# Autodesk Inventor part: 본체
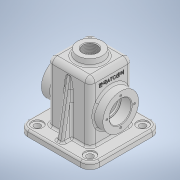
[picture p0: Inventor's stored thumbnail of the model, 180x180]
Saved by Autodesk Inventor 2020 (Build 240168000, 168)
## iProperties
Created: 2021-07
Part Number: 본체
Material: 일반
Document SubType Name: Modeling
Designer: Owner
Density: 1 g/cm^3
Appearance: 기본값
Author: Owner
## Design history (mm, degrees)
sketch "스케치1"
  geometry: L1 (34, 34)-(-34, 34); L2 (-34, 34)-(-34, -34); L3 (-34, -34)-(34, -34); L4 (34, -34)-(34, 34); L5 (34, 34)-(-34, -34); L6 (-34, 34)-(34, -34); 1 further point
  constraints: 12 end point, 2 midpoint, 2 parallel, 1 horizontal, 1 perpendicular
  dimensions: "d0" = 68 distance of L3.end L2.end; "d1" = 68 distance of L2.end L1.end
extrude "돌출1" new body sketch "스케치1" distance "d2" = 95; taper "d3" = 0 deg
fillet "모깎기1" dims "d4" = 8
feature "쉘1" dims "d5" = 5
node "작업 평면1"
sketch "스케치2"
  geometry: C1 r 20 at (0, 0); 1 further point
  constraints: 1 centre point, 1 coincident
  dimensions: "d7" = 40 diameter of C1
extrude "돌출2" join sketch "스케치2" stored distance "d8" = 95; taper "d9" = 8 deg
sketch "스케치3"
  geometry: L1 (57, -57)-(-57, -57); L2 (-57, -57)-(-57, 57); L3 (-57, 57)-(57, 57); L4 (57, 57)-(57, -57); L5 (57, -57)-(-57, 57); L6 (-57, -57)-(57, 57); L7 (-29, -26)-(-29, 26) reference; L8 (26, -29)-(-26, -29) reference; L9 (29, 26)-(29, -26) reference; L10 (-26, 29)-(26, 29) reference; A1 r 3 centre (-26, -26) between (-29, -26) and (-26, -29) reference; A2 r 3 centre (26, -26) between (26, -29) and (29, -26) reference; A3 r 3 centre (-26, 26) between (-26, 29) and (-29, 26) reference; A4 r 3 centre (26, 26) between (29, 26) and (26, 29) reference; 1 further point
  constraints: 12 end point, 2 midpoint, 2 parallel, 1 horizontal, 1 perpendicular
  dimensions: "d10" = 114 distance of L2.end L3.end; "d11" = 114 distance of L1.end L2.end
extrude "돌출3" join sketch "스케치3" distance "d12" = 10; taper "d13" = 0 deg
fillet "모깎기2" dims "d14" = 15
sketch "스케치4"
  geometry: A1 r 15 centre (42, -42) between (42, -57) and (57, -42) reference; A2 r 15 centre (-42, -42) between (-57, -42) and (-42, -57) reference; A3 r 15 centre (42, 42) between (57, 42) and (42, 57) reference; A4 r 15 centre (-42, 42) between (-42, 57) and (-57, 42) reference; 5 further points
  constraints: 4 coincident
hole "구멍1" sketch "스케치4" at (42, -42), (-42, -42), (42, 42), (-42, 42) diameter "d15" = 10; stored, may be unused: countersink angle "d19" = 90 deg, drill point angle "d21" = 0 deg; dims "d16" = 8, "d17" = 18, "d18" = 2, "d20" = 10
sketch "스케치5"
  geometry: C1 r 20 at (0, 0) reference; 2 further points
  constraints: 1 coincident
hole "구멍2" sketch "스케치5" at (0, 0) diameter "d22" = 22.83494; stored, may be unused: countersink angle "d26" = 90 deg, drill point angle "d28" = 0 deg; dims "d23" = 20, "d24" = 18, "d25" = 2, "d27" = 20
node "작업 평면2"
sketch "스케치6"
  geometry: C1 r 28.5 at (42, 0); 1 further point
  constraints: 1 centre point, 1 horizontal alignment
  dimensions: "d30" = 57 diameter of C1; "d31" = 42 distance of point (0, 0) C1.centre
extrude "돌출4" join sketch "스케치6" stored distance "d32" = 10; taper "d33" = 0 deg
sketch "스케치7"
  geometry: C1 r 28.5 at (0, 0) reference; C2 r 17.5 at (0, 0); 1 further point
  constraints: 1 centre point, 1 coincident
  dimensions: "d34" = 35 diameter of C2
extrude "돌출5" cut sketch "스케치7" distance "d35" = 17; taper "d36" = 0 deg
sketch "스케치8"
  geometry: C1 r 17.5 at (0, 0) reference; C2 r 15 at (0, 0); 1 further point
  constraints: 1 centre point, 1 coincident
  dimensions: "d37" = 30 diameter of C2
extrude "돌출6" cut sketch "스케치8" stored distance "d38" = 17; taper "d39" = 0 deg
sketch "스케치9"
  geometry: L1 (6, 18)-(46, 18) reference; L2 (-8, 0)-(-8, -87) reference; 2 further points
  constraints: 1 other
  dimensions: "d40" = 25 distance from line of L1 point (26, -7); "d41" = 34 distance from line of L2 point (26, -7)
feature "엠보싱1" sketch "스케치9" dims "d0" = 68, "d1" = 68, "d42" = 0.5, "d43" = 0
sketch "스케치10" dims "d44" = 44
  geometry: C1 r 17.5 at (0, 0) reference; C2 r 15 at (0, 0) reference; 3 further points
  constraints: 2 vertical alignment, 1 coincident, 2 other
hole "구멍3" sketch "스케치10" at (0, 22) diameter "d45" = 3.242; stored, may be unused: countersink angle "d49" = 90 deg, drill point angle "d51" = 118 deg; dims "d46" = 8, "d47" = 18, "d48" = 2, "d50" = 10
sketch "스케치11"
  geometry: L1 (61.199, 38.209)-(0, 49); L2 (61.78, -38.107)-(0, -49); L3 (-10, 57)-(0, 57) reference; L4 (0, -57)-(-10, -57) reference; L5 (0, 51)-(0, 33) reference; L6 (0, 57)-(0, 42) reference; L7 (0, -33)-(0, -51) reference; L8 (0, -42)-(0, -57) reference; 1 further point
  constraints: 4 end point, 2 point on line
  dimensions: "d55" = 10 deg angle of L1 L3; "d56" = 10 deg angle of L2 L4; "d57" = 8 vertical distance of L3.start L1.end; "d58" = 8 distance from line of L4 L2.end
feature "리브1" sketch "스케치11" dims "d59" = 1, "d60" = 10, "d61" = 0, "d62" = 0, "d63" = 1, "d64" = 1
fillet "모깎기3" dims "d65" = 3
fillet "모깎기4" dims "d66" = 3
fillet "모깎기5" dims "d67" = 3
fillet "모깎기6" dims "d68" = 3
fillet "모깎기7" dims "d69" = 0.3
chamfer "모따기1" distance "d70" = 1; stored, may be unused: second distance "d71" = 2, angle "d72" = 45 deg
node "솔리드1"
mirror "미러1"
pattern_circular "원형 패턴1" dims angle "d53" = 360 deg
mirror "미러2"
mirror "미러3"
feature "A9D066F2-1C7D-4E18-AEED-F7BC21143FA4" dims "d15" = 10, "d16" = 8, "d17" = 18, "d18" = 2, "d19" = 90 deg, "d20" = 10, "d21" = 0
other parameters: "d6" = -105, "d29" = -49
